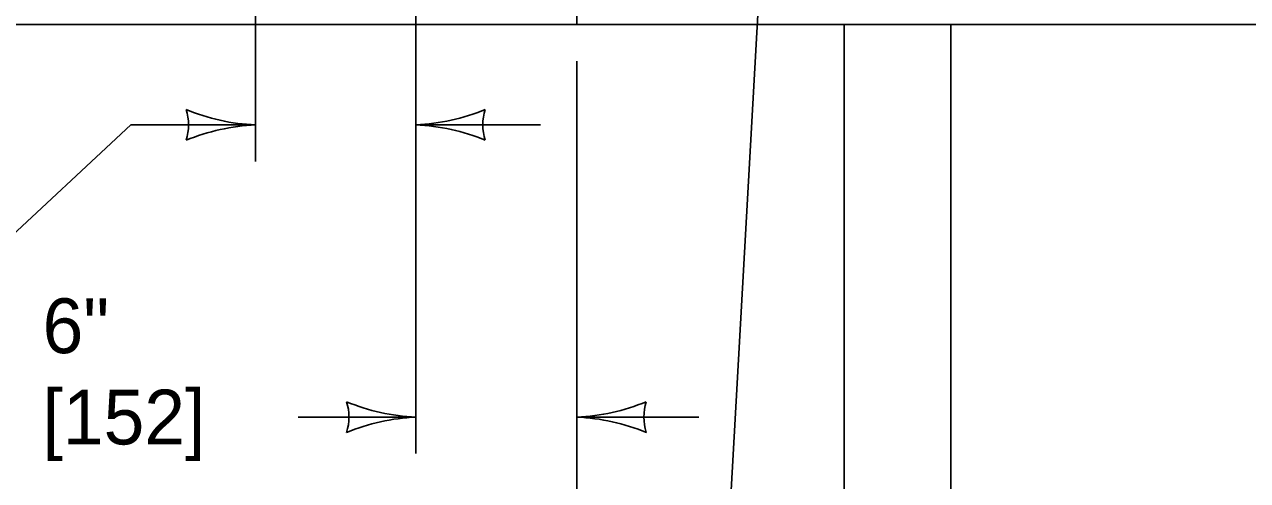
# Model space of a CAD drawing. Extents: x 49983 to 50021, y 49963.5 to 50011.4.
# Drawn here: x 50004.473 to 50005.814, y 49993.967 to 49994.466 of the extents above; entities that cross this region are included whole.
import ezdxf

# ---------------------------------------------------------------- set-up
doc = ezdxf.new("R2010")
doc.units = 0
for name, color, linetype in [('Level 1', 7, 'Continuous'), ('Level 2', 7, 'Continuous'), ('Level 3', 7, 'Continuous'), ('Level 4', 7, 'Continuous'), ('Level 5', 7, 'Continuous')]:
    doc.layers.add(name, color=color, linetype=linetype)

msp = doc.modelspace()

# ---------------------------------------------------------------- linework, layer by layer
at = {"layer": 'Level 1'}
for p, q in [((50005.0789, 49994.8968), (50005.0789, 49994.4663)), ((50005.1046, 49994.4663), (50000.7665, 49994.4663)), ((50015.1755, 49994.4663), (50005.1046, 49994.4663))]:
    msp.add_line(p, q, dxfattribs=at)
at = {"layer": 'Level 3'}
for p, q in [((50005.2987, 49994.8617), (50005.219, 49993.4395)), ((50005.0789, 49994.4263), (50005.0789, 49993.7716)), ((50004.2722, 49994.0616), (50004.5899, 49994.3564)), ((50004.7264, 49994.3564), (50004.5899, 49994.3564)), ((50005.0388, 49994.3564), (50004.9023, 49994.3564)), ((50004.9023, 49994.0364), (50004.7734, 49994.0364)), ((50005.2125, 49994.0364), (50005.0789, 49994.0364))]:
    msp.add_line(p, q, dxfattribs=at)
for centre, radius, start, end in [((50004.7356, 49994.5785), 0.2223, 247.456, 267.6395), ((50004.5982, 49994.3564), 0.0548, 342.1388, 17.8612), ((50004.8908, 49994.5891), 0.233, 272.8273, 292.0772), ((50005.0305, 49994.3564), 0.0548, 162.1388, 197.8612), ((50004.7379, 49994.1237), 0.233, 92.8273, 112.0772), ((50004.8931, 49994.1343), 0.2223, 67.456, 87.6395), ((50004.9114, 49994.2585), 0.2223, 247.456, 267.6395), ((50004.7741, 49994.0364), 0.0548, 342.1388, 17.8612), ((50005.0697, 49994.2585), 0.2223, 272.3605, 292.544), ((50005.2071, 49994.0364), 0.0548, 162.1388, 197.8612), ((50004.9138, 49993.8037), 0.233, 92.8273, 112.0772), ((50005.0674, 49993.8037), 0.233, 67.9228, 87.1727)]:
    msp.add_arc(centre, radius, start, end, dxfattribs=at)
at = {"layer": 'Level 4'}
for p, q in [((50005.3717, 49993.1779), (50005.3717, 49994.4663)), ((50005.4888, 49994.4663), (50005.4888, 49993.1779))]:
    msp.add_line(p, q, dxfattribs=at)
at = {"layer": 'Level 5'}
for p, q in [((50004.7264, 49995.0648), (50004.7264, 49994.3164)), ((50004.9023, 49995.0648), (50004.9023, 49993.9964))]:
    msp.add_line(p, q, dxfattribs=at)

# ---------------------------------------------------------------- texts
at = {"layer": 'Level 2'}
for s, p in [('6"', (50004.493, 49994.1064)), ('[152]', (50004.493, 49994.0064))]:
    msp.add_text(s, height=0.06, dxfattribs=at).set_placement(p)

doc.saveas('drawing.dxf')
